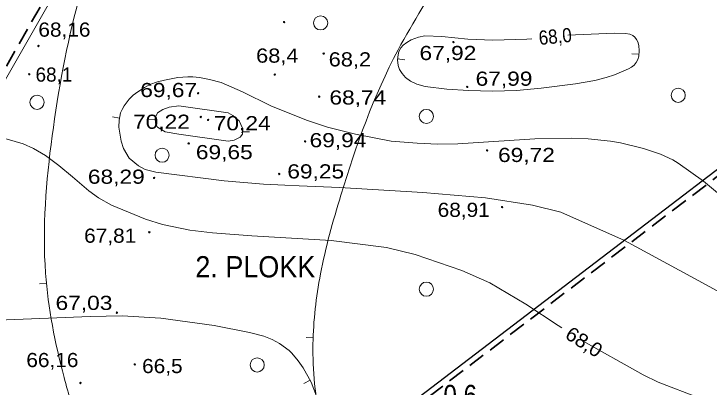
# Model space of a CAD drawing. Extents: x 628176 to 629009, y 6439913 to 6440496.
# Drawn here: x 628433.7 to 628531.9, y 6440288.3 to 6440341 of the extents above; entities that cross this region are included whole.
import ezdxf
from ezdxf.enums import TextEntityAlignment as Align

# ---------------------------------------------------------------- set-up
doc = ezdxf.new("R2010")
doc.units = 0
doc.header["$LTSCALE"] = 0.8
doc.linetypes.add('MEDIUM_DASHED', pattern=[4.5, 3, -1.5])
for name, color, linetype, lineweight in [('1', 7, 'Continuous', 13), ('11', 7, 'Continuous', 13), ('14', 7, 'Continuous', 25), ('16', 7, 'Continuous', 13), ('21', 7, 'MEDIUM_DASHED', 35), ('3', 7, 'Continuous', 13)]:
    doc.layers.add(name, color=color, linetype=linetype, lineweight=lineweight)

msp = doc.modelspace()

# ---------------------------------------------------------------- hatches: boundary and pattern name
at = {"layer": '1'}
for points in [[(628471.9794, 6440339.8264, 1), (628471.7794, 6440339.8264, 1)], [(628495.9149, 6440337.0078, 1), (628495.7149, 6440337.0078, 1)], [(628437.266, 6440336.4598, 1), (628437.066, 6440336.4598, 1)], [(628477.581, 6440335.3922, 1), (628477.381, 6440335.3922, 1)], [(628435.9711, 6440332.4773, 1), (628435.7711, 6440332.4773, 1)], [(628470.6642, 6440332.4265, 1), (628470.4642, 6440332.4265, 1)], [(628459.8424, 6440329.79, 1), (628459.6424, 6440329.79, 1)], [(628497.859, 6440330.6754, 1), (628497.659, 6440330.6754, 1)], [(628476.9526, 6440329.3023, 1), (628476.7526, 6440329.3023, 1)], [(628460.2079, 6440326.4306, 1), (628460.0079, 6440326.4306, 1)], [(628461.2451, 6440326.0171, 1), (628461.0451, 6440326.0171, 1)], [(628474.956, 6440322.9761, 1), (628474.756, 6440322.9761, 1)], [(628458.5045, 6440322.692, 1), (628458.3045, 6440322.692, 1)], [(628500.6722, 6440321.712, 1), (628500.4722, 6440321.712, 1)], [(628471.3052, 6440318.3838, 1), (628471.1052, 6440318.3838, 1)], [(628453.6197, 6440317.8345, 1), (628453.4197, 6440317.8345, 1)], [(628502.7942, 6440313.6992, 1), (628502.5942, 6440313.6992, 1)], [(628452.941, 6440310.1603, 1), (628452.741, 6440310.1603, 1)], [(628448.3599, 6440298.7949, 1), (628448.1599, 6440298.7949, 1)], [(628450.8919, 6440291.4869, 1), (628450.6919, 6440291.4869, 1)], [(628443.2145, 6440288.8642, 1), (628443.0145, 6440288.8642, 1)]]:
    msp.add_hatch(color=256, dxfattribs=at).paths.add_polyline_path(points)

# ---------------------------------------------------------------- linework, layer by layer
for centre, radius in [((628477.0531, 6440339.7163), 1), ((628471.8794, 6440339.8264), 0.1), ((628495.8149, 6440337.0078), 0.1), ((628437.166, 6440336.4598), 0.1), ((628477.481, 6440335.3922), 0.1), ((628435.8711, 6440332.4773), 0.1), ((628470.5642, 6440332.4265), 0.1), ((628459.7424, 6440329.79), 0.1), ((628497.759, 6440330.6754), 0.1), ((628527.5837, 6440329.4978), 1), ((628436.977, 6440328.5022), 1), ((628476.8526, 6440329.3023), 0.1), ((628491.9882, 6440326.5108), 1), ((628460.1079, 6440326.4306), 0.1), ((628461.1451, 6440326.0171), 0.1), ((628474.856, 6440322.9761), 0.1), ((628454.6503, 6440321.0346), 1), ((628458.4045, 6440322.692), 0.1), ((628500.5722, 6440321.712), 0.1), ((628471.2052, 6440318.3838), 0.1), ((628453.5197, 6440317.8345), 0.1), ((628502.6942, 6440313.6992), 0.1), ((628452.841, 6440310.1603), 0.1), ((628491.9882, 6440302.1167), 1), ((628448.2599, 6440298.7949), 0.1), ((628450.7919, 6440291.4869), 0.1), ((628468.092, 6440291.4132), 1), ((628443.1145, 6440288.8642), 0.1)]:
    msp.add_circle(centre, radius, dxfattribs=at)
at = {"layer": '11'}
for points in [[(628595.11, 6440426.87), (628573.75, 6440350.05), (628485.59, 6440282.78), (628547.63, 6440210.77)], [(628479.31, 6440413.61), (628403.76, 6440281.52), (628439.01, 6440242.62), (628472.21, 6440157.1)]]:
    msp.add_lwpolyline(points, dxfattribs=at)
at = {"layer": '14'}
msp.add_lwpolyline([(628595.11, 6440426.87), (628573.75, 6440350.05), (628485.59, 6440282.78)], dxfattribs=at)
at = {"layer": '16'}
for p, q in [((628437.31, 6440302.89), (628438.31, 6440302.98)), ((628475, 6440295.29), (628476, 6440295.25))]:
    msp.add_line(p, q, dxfattribs=at)
for points in [[(628523.86, 6440425.63), (628523.12, 6440415.76), (628522.56, 6440410.73), (628519.12, 6440396.74), (628513.8, 6440381.86), (628510.45, 6440374.81), (628499.31, 6440356.42), (628494.72, 6440347.58), (628488, 6440335.91), (628479.91, 6440315.37), (628477.03, 6440304.26), (628475.97, 6440294.36), (628477.03, 6440283.22), (628480.57, 6440271.2), (628486.05, 6440256.7), (628486.58, 6440255.49)], [(628500.95, 6440423.21), (628492.76, 6440414.83), (628485.87, 6440407.94), (628478.97, 6440401.05), (628470.41, 6440392.85), (628466.49, 6440387.45), (628459.04, 6440376.65), (628449.92, 6440361.56), (628445.26, 6440350.76), (628442.84, 6440342.93), (628439.11, 6440323.75), (628438.18, 6440304.38), (628440.79, 6440289.66), (628442.84, 6440282.59), (628446.19, 6440272.53), (628459.6, 6440244.4), (628464.91, 6440235.24)]]:
    msp.add_spline(points, degree=3, dxfattribs=at)
at = {"layer": '21'}
for points in [[(628595.48, 6440425.23), (628574.45, 6440349.57), (628486.75, 6440282.66), (628547.03, 6440212.69)], [(628476.73, 6440410.71), (628402.77, 6440281.42), (628438.32, 6440242.19), (628470.2, 6440160.05)]]:
    msp.add_lwpolyline(points, dxfattribs=at)
at = {"layer": '3'}
for p, q in [((628494.18, 6440337.78), (628497.83, 6440337.42)), ((628512, 6440338), (628518.56, 6440338.27)), ((628497.83, 6440337.42), (628501.38, 6440337.28)), ((628501.38, 6440337.28), (628506.17, 6440337.42)), ((628506.17, 6440337.42), (628506.88, 6440337.49)), ((628521.02, 6440335.37), (628522.02, 6440335.3)), ((628488.93, 6440334.51), (628487.93, 6440334.62)), ((628458.28, 6440332.11), (628459, 6440332.09)), ((628459, 6440332.09), (628459.92, 6440332)), ((628461.34, 6440331.72), (628459.92, 6440332)), ((628454, 6440331.38), (628452.93, 6440331)), ((628461.34, 6440331.72), (628463, 6440331.32)), ((628504.73, 6440330.18), (628501.35, 6440330.08)), ((628508.2, 6440330.49), (628504.73, 6440330.18)), ((628450.54, 6440329.49), (628450, 6440328.94)), ((628464, 6440327), (628457, 6440328)), ((628447.65, 6440326.47), (628448.63, 6440326.27)), ((628452.68, 6440326.04), (628453.68, 6440326.08)), ((628457, 6440324), (628464, 6440323)), ((628467, 6440324.32), (628466, 6440324.33)), ((628519.41, 6440322.77), (628518, 6440323)), ((628493.62, 6440322.59), (628496.45, 6440322.66)), ((628527.59, 6440319.93), (628526.8, 6440320.38)), ((628452.24, 6440319), (628451.33, 6440319.51)), ((628531.18, 6440317.35), (628527.59, 6440319.93)), ((628452.24, 6440319), (628453.78, 6440318.63)), ((628453.78, 6440318.63), (628463.4, 6440317.4)), ((628463.4, 6440317.4), (628468.96, 6440316.92)), ((628468.96, 6440316.92), (628472, 6440316.78)), ((628472, 6440316.78), (628474, 6440316.73)), ((628500.33, 6440315), (628507, 6440314)), ((628511, 6440313), (628507, 6440314)), ((628454.7, 6440311.26), (628458.56, 6440310.45)), ((628461.78, 6440310.05), (628458.56, 6440310.45)), ((628461.78, 6440310.05), (628467.31, 6440309.64)), ((628444.47, 6440298.24), (628430.86, 6440297.72)), ((628449, 6440298.35), (628444.47, 6440298.24)), ((628511.14, 6440296.66), (628510.6, 6440297)), ((628522.62, 6440290), (628513.75, 6440295)), ((628524.75, 6440289), (628522.62, 6440290)), ((628474.69, 6440288.78), (628475.56, 6440289.27)), ((628524.75, 6440289), (628530.62, 6440286.71))]:
    msp.add_line(p, q, dxfattribs=at)
for points in [[(628494.18, 6440337.78), (628491.76, 6440337.9), (628490.86, 6440337.71), (628489.83, 6440337.33), (628489.22, 6440336.97), (628488.73, 6440336.58), (628488.38, 6440336.18), (628488.1, 6440335.66), (628487.99, 6440335.19), (628487.92, 6440334.48), (628488, 6440333.69), (628488.21, 6440333.12), (628488.55, 6440332.58), (628489.03, 6440332), (628489.76, 6440331.48), (628490.64, 6440331.06), (628491.8, 6440330.75), (628494.89, 6440330.35), (628497.94, 6440330.15), (628501.35, 6440330.08)], [(628508.2, 6440330.49), (628513.06, 6440331.11), (628515.79, 6440331.6), (628517.4, 6440332), (628518.59, 6440332.39), (628520.55, 6440333.21), (628521, 6440333.48), (628521.37, 6440333.77), (628521.64, 6440334.12), (628521.88, 6440334.57), (628522, 6440335.01), (628522.06, 6440335.79), (628522, 6440336.52), (628521.88, 6440337.06), (628521.71, 6440337.37), (628521.43, 6440337.71), (628521.15, 6440337.94), (628520.73, 6440338.13), (628520.15, 6440338.22), (628518.56, 6440338.27)], [(628454, 6440331.38), (628455, 6440331.65), (628456.89, 6440332), (628458.28, 6440332.11)], [(628450.54, 6440329.49), (628451.2, 6440330), (628452.16, 6440330.6), (628452.93, 6440331)], [(628463, 6440331.32), (628466, 6440330), (628470, 6440328), (628475.06, 6440326), (628478, 6440325), (628482, 6440324), (628487, 6440323)], [(628449.18, 6440322), (628448.84, 6440323), (628448.54, 6440325), (628448.58, 6440326), (628448.78, 6440327), (628449, 6440327.49), (628449.3, 6440328), (628450, 6440328.94)], [(628457, 6440328), (628455.64, 6440327.8), (628454.77, 6440327.48), (628454, 6440327)], [(628454, 6440327), (628453.68, 6440326.29), (628453.7, 6440325.52), (628454, 6440325)], [(628466, 6440324), (628466, 6440324.86), (628465.54, 6440325.88), (628464.65, 6440326.63), (628464, 6440327)], [(628454, 6440325), (628455.08, 6440324.35), (628457, 6440324)], [(628464, 6440323), (628464.84, 6440323.16), (628465.66, 6440323.6), (628466, 6440324)], [(628447.49, 6440314), (628445.68, 6440315), (628444.27, 6440316), (628441.97, 6440318), (628440.06, 6440319.6), (628438.15, 6440321), (628436.46, 6440322), (628435, 6440322.62), (628432.73, 6440323.31), (628430.72, 6440323.63), (628428.63, 6440323.7), (628426, 6440323.44), (628422.08, 6440322.6)], [(628487, 6440323), (628490.68, 6440322.72), (628493.62, 6440322.59)], [(628518, 6440323), (628514.85, 6440323.33), (628512.57, 6440323.44), (628507.33, 6440323.33), (628496.45, 6440322.66)], [(628449.18, 6440322), (628450, 6440320.6), (628451.33, 6440319.51)], [(628526.8, 6440320.38), (628525.06, 6440321.17), (628522.7, 6440322), (628519.41, 6440322.77)], [(628535.74, 6440313.55), (628534, 6440315), (628531.18, 6440317.35)], [(628500.33, 6440315), (628491.51, 6440315.79), (628479.73, 6440316.48), (628474, 6440316.73)], [(628454.7, 6440311.26), (628452.32, 6440312), (628447.49, 6440314)], [(628511, 6440313), (628520, 6440309), (628531, 6440303), (628545.67, 6440295)], [(628510.6, 6440297), (628506.06, 6440300), (628500.97, 6440303), (628497, 6440304.73), (628490.41, 6440307), (628486.34, 6440308), (628478.56, 6440309), (628467.31, 6440309.64)], [(628467, 6440296), (628462, 6440297), (628454.46, 6440298.01), (628449, 6440298.35)], [(628467, 6440296), (628469, 6440295.49), (628470.2, 6440295), (628471.25, 6440294.46), (628472.62, 6440293.46), (628473, 6440293.07), (628473.88, 6440292), (628474.57, 6440291), (628475.71, 6440289), (628476.48, 6440287), (628476.98, 6440285), (628477.09, 6440283.56), (628477.08, 6440282.88), (628476.98, 6440281)]]:
    msp.add_lwpolyline(points, dxfattribs=at)

# ---------------------------------------------------------------- texts
at = {"layer": '1'}
for s, width, p in [('68,16', 1.1, (628437.16, 6440337.77)), ('68,4', 1.15, (628467.93, 6440334.1)), ('67,92', 1.2, (628491.02, 6440334.47)), ('68,2', 1.15, (628478.19, 6440333.57)), ('67,99', 1.2, (628498.95, 6440330.84)), ('69,67', 1.2, (628451.56, 6440329.24)), ('68,74', 1.2, (628478.29, 6440328.19)), ('70,22', 1.2, (628450.54, 6440324.76)), ('70,24', 1.2, (628461.95, 6440324.55)), ('69,94', 1.2, (628475.49, 6440322.16)), ('69,65', 1.2, (628459.42, 6440320.47)), ('69,72', 1.2, (628502.12, 6440320.07)), ('68,29', 1.2, (628444.16, 6440317)), ('69,25', 1.2, (628472.34, 6440317.75)), ('68,91', 1.1, (628493.59, 6440312.32)), ('67,81', 1.1, (628443.63, 6440308.67)), ('67,03', 1.2, (628439.59, 6440299.18)), ('66,16', 1.1, (628435.46, 6440291.11)), ('66,5', 1.1, (628451.82, 6440290.26))]:
    msp.add_text(s, height=2, dxfattribs=dict(at, width=width)).set_placement(p)
msp.add_text('68,1', height=2, dxfattribs=at).set_placement((628436.76, 6440331.42))
at = {"layer": '11', "width": 0.85}
msp.add_text('0,6', height=3, dxfattribs=at).set_placement((628496.775, 6440285.6), align=Align.CENTER)
at = {"layer": '21', "width": 0.95}
msp.add_text('2. PLOKK', height=3, dxfattribs=at).set_placement((628467.82, 6440303.78), align=Align.CENTER)
at = {"layer": '3'}
for rotation, width, p in [(5.71, 0.9, (628507.97, 6440336.59)), (327.583, 1.05, (628511.44, 6440295.28))]:
    msp.add_text('68,0', height=2, rotation=rotation, dxfattribs=dict(at, width=width)).set_placement(p)

doc.saveas('drawing.dxf')
